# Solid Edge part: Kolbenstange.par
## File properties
Username: bmolnar
Dokumentum tartalom típus: 0
Author: bmolnar
Last saved by: bmolnar
Revision: 97
Sűrűség: 0,000 kg/m^3
Pontosság: 0,990
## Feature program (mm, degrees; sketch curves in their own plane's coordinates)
base feature "unnamed BaseFeature 1"
sketch for "unnamed Protrusion 1" plane through (30, 0, 0) normal (1, 0, 0) x-axis (0, -1, 0)
  circle centre (0, 0) radius 25
extrude "unnamed Protrusion 1" add finite 8.5 along +normal
sketch for "Kihúzás_2" plane through (30, 0, 0) normal (1, 0, 0) x-axis (0, -1, 0)
  circle centre (0, 0) radius 25
extrude "Kihúzás_2" add finite 7.5 along -normal
sketch for "Furat_2" plane through (-320, 0, 0) normal (-1, 0, 0) x-axis (0, 0, -1)
  hole centre (0, 0) bore radius 4.188
hole "Furat_2" nominal diameter 10 finite  ThreadDepth = 17 mm
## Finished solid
Body 1: solid body, 14 faces, 20 edges, 8 vertices.
  Faces by surface: plane 8, cylinder 4, cone 1, torus 1
  Edges by curve: circle 10, line 6, ellipse 2, intersection 2
Bounding box of the edges (mm; curved faces can reach further): 358.500 x 50.000 x 50.000, from (-320, -25, -25) to (38.5, 25, 25).
Cylindrical faces by radius (mm): R4.188 x2, R8 x1, R25 x1
Conical faces (half-angle, radius in mm at the cone's reference point): 45 deg R4.538 x1
Toroidal faces (ring radius, tube radius in mm): R6.3 r1.7 x1
Planar faces by outward normal: +x 1, +z 1, -x 3, -z 1, oblique 2
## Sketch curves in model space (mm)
circle centre (30, 0, 0) radius 25
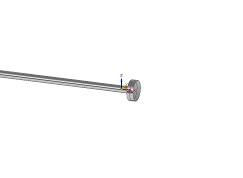
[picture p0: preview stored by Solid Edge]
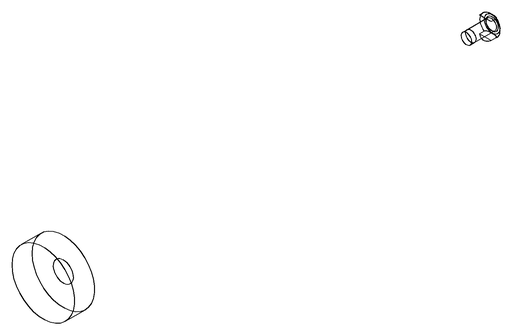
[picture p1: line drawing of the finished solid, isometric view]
